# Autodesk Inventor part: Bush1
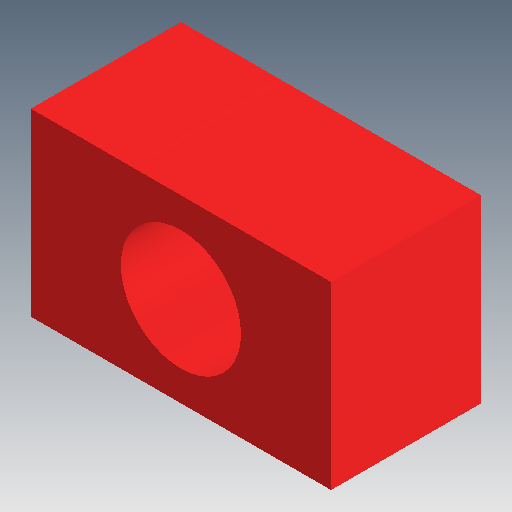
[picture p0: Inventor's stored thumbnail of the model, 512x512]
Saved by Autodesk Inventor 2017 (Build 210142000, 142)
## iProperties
Created: 2015-03
Part Number: Bush1
Document SubType Name: Modeling
Designer: Administrator
Density: 1 g/cm^3
Mass: 0.237168 g
Surface Area: 3.17699 cm^2
Volume: 0.237168 cm^3
Material: Generic
Appearance: Light Red-Orange
Author: Administrator
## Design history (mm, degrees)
sketch "Sketch1"
  geometry: L1 (3, 3)-(3, -3); L2 (3, -3)-(-3, -3); L3 (-3, -3)-(-3, 3); L4 (-3, 3)-(3, 3); L5 (-3, 3)-(-5, 3); L6 (-5, 3)-(-5, -3); L7 (-5, -3)-(-3, -3); L8 (-3, -3)-(-3, 3); L9 (3, -3)-(5, -3); L10 (5, -3)-(5, 3); L11 (5, 3)-(3, 3); L12 (3, 3)-(3, -3); C1 r 2 at (0, 0); 2 further points
  constraints: 24 end point, 4 parallel, 3 equal length, 2 coincident, 2 horizontal, 2 perpendicular, 1 centre point, 1 vertical, 9 other
  dimensions: "d5" = 6 distance of L3.end L1.start; "d24" = 4 diameter of C1; "d25" = 10 distance between parallel lines of L10 L6
extrude "Extrusion1" new body sketch "Sketch1" stored distance "d6" = 5; taper "d7" = 0 deg
body "Solid1"
